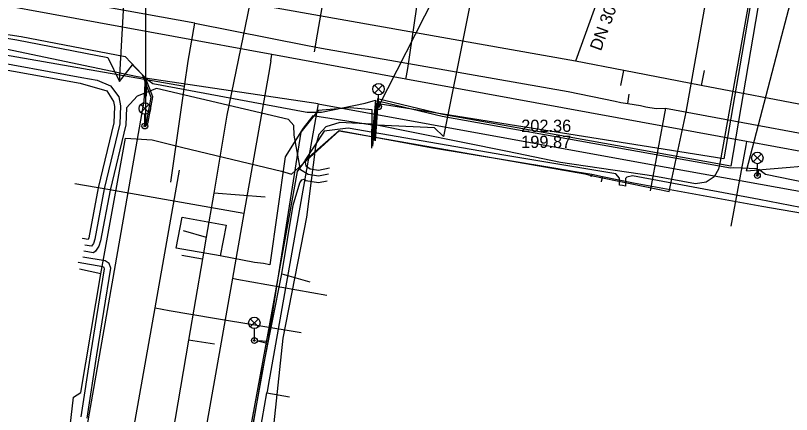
# Model space of a CAD drawing. Extents: x -596228 to -595156, y -1161235 to -1159373.
# Drawn here: x -595929.1 to -595878.3, y -1160349.7 to -1160323.7 of the extents above; entities that cross this region are included whole.
import ezdxf

# ---------------------------------------------------------------- set-up
doc = ezdxf.new("R2010")
doc.units = 0
for name, color, linetype in [('Vrstva 1', 7, 'Continuous'), ('Vrstva 12', 7, 'Continuous'), ('Vrstva 14', 7, 'Continuous'), ('Vrstva 16', 7, 'Continuous'), ('Vrstva 19', 7, 'Continuous'), ('Vrstva 33', 7, 'Continuous'), ('Vrstva 4', 7, 'Continuous'), ('Vrstva 42', 7, 'Continuous'), ('Vrstva 44', 7, 'Continuous'), ('Vrstva 54', 7, 'Continuous'), ('Vrstva 55', 7, 'Continuous'), ('Vrstva 58', 7, 'Continuous'), ('Vrstva 9', 7, 'Continuous')]:
    doc.layers.add(name, color=color, linetype=linetype)

msp = doc.modelspace()

# ---------------------------------------------------------------- linework, layer by layer
at = {"layer": 'Vrstva 1'}
for p, q in [((-595888.65, -1160316.04), (-595892.47, -1160326.63)), ((-595888.649, -1160316.044), (-595892.47, -1160326.63)), ((-595912.78, -1160335.52), (-595916.141, -1160335.27)), ((-595918.228, -1160339.316), (-595916.873, -1160339.558))]:
    msp.add_line(p, q, dxfattribs=at)
at = {"layer": 'Vrstva 12'}
for p, q in [((-595921.13, -1160327.66), (-595929.73, -1160325.84)), ((-595920.63, -1160327.74), (-595921.13, -1160327.66)), ((-595920.63, -1160327.74), (-595920.7, -1160329.26)), ((-595909.31, -1160329.42), (-595920.63, -1160327.74)), ((-595909.31, -1160329.42), (-595912.58, -1160347.84)), ((-595891.4, -1160334.03), (-595890.71, -1160334.18)), ((-595890.71, -1160334.18), (-595890.8, -1160334.52)), ((-595913.63, -1160353.77), (-595912.66, -1160348.33)), ((-595912.66, -1160348.33), (-595911.19, -1160348.59))]:
    msp.add_line(p, q, dxfattribs=at)
for points in [[(-595920.7, -1160329.26), (-595926.32, -1160361.22), (-595928.48, -1160360.84)], [(-595909.31, -1160329.42), (-595887.62, -1160333.37), (-595870.92, -1160336.38), (-595851.25, -1160339.95)], [(-595913.91, -1160351.66), (-595913.82, -1160351.17), (-595912.54, -1160344.18), (-595910.66, -1160333.84), (-595910.07, -1160333.04), (-595907.93, -1160331.17), (-595901.94, -1160332.28), (-595894.02, -1160333.59)], [(-595894.02, -1160333.59), (-595892.36, -1160333.86), (-595891.4, -1160334.03)], [(-595890.71, -1160334.18), (-595888.67, -1160334.6), (-595880.28, -1160336.12), (-595874.32, -1160337.13), (-595873.61, -1160337.32)], [(-595912.58, -1160347.84), (-595912.63, -1160348.13), (-595912.66, -1160348.33)]]:
    msp.add_lwpolyline(points, dxfattribs=at)
at = {"layer": 'Vrstva 14'}
for p, q in [((-595912.4, -1160326.61), (-595912.327, -1160326.199)), ((-595912.4, -1160326.61), (-595912.56, -1160327.515)), ((-595903.564, -1160327.806), (-595903.525, -1160327.591))]:
    msp.add_line(p, q, dxfattribs=at)
for points in [[(-595903.525, -1160327.591), (-595903.438, -1160327.11), (-595895.992, -1160276.218), (-595895.362, -1160271.913), (-595894.416, -1160266.829), (-595893.077, -1160257.958), (-595892.847, -1160256.335), (-595887.94, -1160223.167), (-595881.65, -1160186.81), (-595876.814, -1160159.541), (-595869.649, -1160117.522), (-595863.209, -1160078.856), (-595858.091, -1160048.124), (-595857.576, -1160045.207), (-595855.994, -1160045.422), (-595855.543, -1160042.523), (-595857.05, -1160042.292), (-595850.5, -1160006.311), (-595840.026, -1160007.969)], [(-595912.327, -1160326.199), (-595944.525, -1160320.296), (-595964.314, -1160316.668), (-595981.5, -1160313.518), (-595993.326, -1160311.35), (-595998.98, -1160310.314), (-596012.243, -1160307.882), (-596018.266, -1160306.788), (-596020.483, -1160306.371), (-596031.546, -1160304.536), (-596031.549, -1160304.535)], [(-595903.564, -1160327.806), (-595911.269, -1160326.394), (-595912.327, -1160326.199)], [(-595912.56, -1160327.515), (-595914.166, -1160336.603), (-595914.913, -1160340.831), (-595917.737, -1160356.816), (-595918.916, -1160363.488), (-595919.224, -1160365.229), (-595921.006, -1160375.317), (-595921.479, -1160377.993), (-595922.856, -1160385.788), (-595923.243, -1160387.979), (-595923.737, -1160390.772), (-595924.81, -1160396.848), (-595925.361, -1160399.964), (-595925.421, -1160400.293), (-595926.258, -1160405.043), (-595926.951, -1160408.967), (-595927.505, -1160412.107), (-595927.792, -1160413.727), (-595928.476, -1160417.596), (-595928.908, -1160420.384), (-595929.827, -1160426.314), (-595930.81, -1160432.66), (-595928.636, -1160435.746)], [(-595796.62, -1160347.3), (-595824.314, -1160342.334), (-595828.542, -1160341.559), (-595835.203, -1160340.338), (-595848.129, -1160337.968), (-595856.324, -1160336.466), (-595859.13, -1160335.952), (-595871.786, -1160333.632), (-595881.289, -1160331.89), (-595903.564, -1160327.806)], [(-595881.289, -1160331.89), (-595881.335, -1160332.141), (-595882.304, -1160337.424)], [(-595914.166, -1160336.603), (-595923.07, -1160335.03), (-595925.227, -1160334.649)], [(-595914.913, -1160340.831), (-595914.634, -1160340.881), (-595908.728, -1160341.924)]]:
    msp.add_lwpolyline(points, dxfattribs=at)
at = {"layer": 'Vrstva 16'}
for p, q in [((-595889.042, -1160329.399), (-595888.956, -1160328.802)), ((-595886.59, -1160329.7), (-595887.58, -1160335.11))]:
    msp.add_line(p, q, dxfattribs=at)
for points in [[(-595917.38, -1160324.14), (-595937.03, -1160320.6), (-595938.02, -1160320.43), (-595944.42, -1160319.31), (-595959.68, -1160316.64), (-595967.05, -1160315.3), (-595979.197, -1160313.085)], [(-595918.953, -1160334.548), (-595918.06, -1160328.3), (-595917.82, -1160326.64), (-595917.38, -1160324.14)], [(-595917.38, -1160324.14), (-595910, -1160325.618), (-595909.091, -1160325.778), (-595892.958, -1160328.622), (-595889.882, -1160329.258), (-595889.508, -1160329.332), (-595889.042, -1160329.399), (-595888.212, -1160329.541), (-595887.856, -1160329.621), (-595887.183, -1160329.739), (-595886.59, -1160329.7), (-595871.98, -1160332.41), (-595863.04, -1160334.1), (-595856.28, -1160335.39), (-595846.15, -1160336.98), (-595838.77, -1160338.11)], [(-595918.06, -1160328.3), (-595938.26, -1160324.76), (-595938.46, -1160325.84)]]:
    msp.add_lwpolyline(points, dxfattribs=at)
at = {"layer": 'Vrstva 19'}
for points in [[(-595906.726, -1160309.776), (-595909.359, -1160324.873), (-595909.569, -1160326.017)], [(-595937.007, -1160434.731), (-595933.869, -1160420.107), (-595932.707, -1160414.408), (-595931.819, -1160409.92), (-595931.488, -1160408.037), (-595930.76, -1160403.887), (-595930.162, -1160400.514), (-595929.486, -1160396.69), (-595928.868, -1160393.202), (-595928.299, -1160389.952), (-595928.122, -1160388.956), (-595925.699, -1160375.221), (-595925.424, -1160373.699), (-595923.915, -1160365.05), (-595923.881, -1160364.906), (-595921.628, -1160352.081), (-595919.973, -1160342.771), (-595918.382, -1160333.761)], [(-595919.973, -1160342.771), (-595919.056, -1160342.938), (-595916.097, -1160343.43), (-595910.412, -1160344.374)]]:
    msp.add_lwpolyline(points, dxfattribs=at)
at = {"layer": 'Vrstva 33'}
for p, q in [((-595905.617, -1160328.194), (-595905.087, -1160328.724)), ((-595905.617, -1160328.724), (-595905.087, -1160328.194)), ((-595905.352, -1160329.609), (-595905.352, -1160328.834)), ((-595920.909, -1160329.462), (-595920.379, -1160329.992)), ((-595920.909, -1160329.992), (-595920.379, -1160329.462)), ((-595920.644, -1160330.877), (-595920.644, -1160330.102)), ((-595880.835, -1160332.697), (-595880.305, -1160333.227)), ((-595880.835, -1160333.227), (-595880.305, -1160332.697)), ((-595880.57, -1160334.112), (-595880.57, -1160333.337)), ((-595913.745, -1160343.485), (-595913.215, -1160344.015)), ((-595913.745, -1160344.015), (-595913.215, -1160343.485)), ((-595913.48, -1160344.9), (-595913.48, -1160344.125))]:
    msp.add_line(p, q, dxfattribs=at)
for centre, radius in [((-595905.352, -1160328.459), 0.375), ((-595920.644, -1160329.727), 0.375), ((-595905.352, -1160329.609), 0.19), ((-595905.352, -1160329.609), 0.05), ((-595920.644, -1160330.877), 0.19), ((-595920.644, -1160330.877), 0.05), ((-595880.57, -1160332.962), 0.375), ((-595880.57, -1160334.112), 0.19), ((-595880.57, -1160334.112), 0.05), ((-595913.48, -1160343.75), 0.375), ((-595913.48, -1160344.9), 0.19), ((-595913.48, -1160344.9), 0.05)]:
    msp.add_circle(centre, radius, dxfattribs=at)
at = {"layer": 'Vrstva 42'}
msp.add_line((-595911.68, -1160340.548), (-595909.852, -1160341.061), dxfattribs=at)
for points in [[(-595932.932, -1160324.581), (-595929.027, -1160325.242), (-595923.071, -1160326.404), (-595922.307, -1160327.96), (-595920.903, -1160303.182), (-595919.478, -1160301.216), (-595901.62, -1160304.641), (-595898.195, -1160305.065), (-595896.735, -1160305.447), (-595895.931, -1160305.565), (-595896.41, -1160308.706), (-595896.64, -1160309.26), (-595901.111, -1160331.564), (-595901.699, -1160330.991), (-595905.91, -1160330.801), (-595909.662, -1160330.217), (-595910.286, -1160331.011), (-595911.466, -1160332.883), (-595912.47, -1160339.95), (-595912.872, -1160339.865)], [(-595945.819, -1160324.546), (-595945.748, -1160324.061), (-595945.592, -1160324.019), (-595943.697, -1160324.265), (-595936.771, -1160325.507), (-595935.472, -1160325.74), (-595931.446, -1160326.474), (-595924.764, -1160327.692), (-595923.765, -1160327.878), (-595922.887, -1160328.25), (-595922.352, -1160328.96), (-595922.237, -1160329.564), (-595922.28, -1160330.732), (-595923.313, -1160334.991), (-595923.924, -1160338.282), (-595924.007, -1160338.558), (-595924.133, -1160338.73), (-595924.561, -1160338.655)], [(-595935.565, -1160326.153), (-595924.874, -1160328.07), (-595923.125, -1160328.568), (-595922.7, -1160329.267), (-595922.638, -1160329.594), (-595922.678, -1160330.677), (-595923.704, -1160334.907), (-595924.313, -1160338.188), (-595924.343, -1160338.288), (-595924.722, -1160338.221), (-595924.726, -1160338.244)], [(-595922.307, -1160327.96), (-595921.458, -1160326.877), (-595920.565, -1160327.77), (-595920.554, -1160328.916)], [(-595908.631, -1160334.031), (-595909.283, -1160334.161), (-595909.964, -1160334.052), (-595910.47, -1160333.734), (-595910.556, -1160333.262), (-595910.881, -1160331.468), (-595910.888, -1160330.838), (-595911.243, -1160330.449), (-595919.891, -1160328.424), (-595921.155, -1160328.93), (-595921.842, -1160329.685), (-595921.882, -1160330.787), (-595922.922, -1160335.075), (-595923.535, -1160338.376), (-595923.644, -1160338.739), (-595923.873, -1160339.053), (-595924.003, -1160339.16), (-595924.631, -1160339.049)], [(-595872.34, -1160337.244), (-595880.463, -1160335.669), (-595888.734, -1160334.137), (-595889.101, -1160334.217), (-595889.194, -1160334.307), (-595889.203, -1160334.813), (-595889.399, -1160334.773), (-595889.599, -1160334.743), (-595889.587, -1160334.279), (-595889.825, -1160334.011), (-595897.161, -1160332.783), (-595907.35, -1160331.02), (-595908.902, -1160331.217), (-595910.173, -1160333.129), (-595910.108, -1160333.489), (-595909.82, -1160333.67), (-595909.291, -1160333.755), (-595908.556, -1160333.609)], [(-595911.68, -1160340.548), (-595910.946, -1160336.044), (-595910.501, -1160334.597), (-595910.383, -1160334.386), (-595910.226, -1160334.36), (-595910.108, -1160334.434), (-595909.275, -1160334.567), (-595908.706, -1160334.453)], [(-595912.872, -1160339.865), (-595913.463, -1160339.796), (-595915.71, -1160339.36), (-595918.595, -1160338.851), (-595918.205, -1160336.826), (-595915.326, -1160337.367), (-595915.71, -1160339.36)], [(-595924.413, -1160349.983), (-595923.788, -1160345.83), (-595922.869, -1160340.179), (-595922.985, -1160339.859), (-595923.25, -1160339.697), (-595924.7, -1160339.442)], [(-595924.805, -1160349.897), (-595924.184, -1160345.768), (-595923.281, -1160340.217), (-595923.313, -1160340.127), (-595923.393, -1160340.079), (-595924.999, -1160339.795), (-595924.995, -1160339.771)], [(-595915.042, -1160370.404), (-595916.313, -1160370.234), (-595916.762, -1160370.071), (-595916.917, -1160369.718), (-595916.266, -1160365.38), (-595916.097, -1160364.525), (-595914.555, -1160356.21), (-595912.957, -1160346.91), (-595911.68, -1160340.548)]]:
    msp.add_lwpolyline(points, dxfattribs=at)
at = {"layer": 'Vrstva 44'}
msp.add_lwpolyline([(-595879.564, -1160313.987), (-595883.002, -1160333.198), (-595883.107, -1160333.686), (-595883.405, -1160334.19), (-595883.921, -1160334.544), (-595884.612, -1160334.658), (-595887.338, -1160334.157), (-595893.448, -1160333.257), (-595896.919, -1160332.531), (-595905.801, -1160330.747), (-595907.892, -1160330.653), (-595908.804, -1160330.924), (-595909.261, -1160331.432), (-595909.489, -1160332.217), (-595910.064, -1160336.838), (-595911.622, -1160344.756), (-595912.375, -1160351.925)], dxfattribs=at)
at = {"layer": 'Vrstva 54'}
for p, q in [((-595920.59, -1160330.87), (-595920.58, -1160309.17)), ((-595905.35, -1160329.62), (-595897.2, -1160313.58)), ((-595879.08, -1160325.37), (-595878.31, -1160322.44)), ((-595881.29, -1160333.8), (-595879.08, -1160325.37)), ((-595881.29, -1160333.8), (-595848.05, -1160331.08))]:
    msp.add_line(p, q, dxfattribs=at)
at = {"layer": 'Vrstva 55'}
for points in [[(-595899.01, -1160302.475), (-595898.851, -1160302.449), (-595898.714, -1160302.619), (-595898.303, -1160303.953), (-595897.422, -1160304.755), (-595897.682, -1160307.978), (-595897.18, -1160308.657), (-595895.88, -1160309.31), (-595895.773, -1160309.364), (-595892.5, -1160311.007), (-595890.732, -1160311.409), (-595881.701, -1160313.199), (-595878.928, -1160313.669), (-595882.299, -1160333.495), (-595901.158, -1160330.111), (-595905.425, -1160329.09), (-595905.669, -1160331.811)], [(-595901.76, -1160303.617), (-595900.5, -1160305.57), (-595899.058, -1160306.768), (-595898.651, -1160307.058), (-595897.37, -1160308.863), (-595892.714, -1160311.365), (-595879.502, -1160313.984), (-595882.762, -1160333.016), (-595905.518, -1160329.407), (-595905.751, -1160332.201)], [(-595937.08, -1160323.76), (-595928.74, -1160325.02), (-595921.94, -1160326.33), (-595920.809, -1160327.51), (-595920.252, -1160328.986), (-595920.539, -1160330.587), (-595920.558, -1160330.665), (-595920.54, -1160330.84), (-595920.442, -1160330.694), (-595920.421, -1160330.613), (-595920.128, -1160328.974), (-595920.598, -1160327.731), (-595920.56, -1160327.77), (-595920.13, -1160328.09), (-595910.145, -1160329.939), (-595910.03, -1160329.96), (-595909.09, -1160329.98), (-595906.22, -1160329.38), (-595905.554, -1160329.186), (-595905.787, -1160331.789)], [(-595905.55, -1160331.833), (-595905.386, -1160329.409), (-595905.312, -1160329.246), (-595905.371, -1160329.484), (-595905.32, -1160329.62), (-595905.238, -1160329.507), (-595905.194, -1160329.268), (-595901.182, -1160330.229), (-595882.321, -1160333.612), (-595882.11, -1160333.59), (-595880.6, -1160333.648), (-595880.615, -1160334.016), (-595880.56, -1160334.15), (-595880.494, -1160334.01), (-595880.482, -1160333.692), (-595880.03, -1160334.02), (-595870.57, -1160335.97)], [(-595905.802, -1160332.325), (-595905.763, -1160329.822), (-595907.213, -1160329.696), (-595909.31, -1160329.87), (-595910.44, -1160331.28), (-595912.59, -1160344.96), (-595913.28, -1160344.91), (-595912.62, -1160345.07), (-595917.45, -1160371.78), (-595918.01, -1160371.63), (-595917.64, -1160371.78), (-595921.92, -1160396.92), (-595922.59, -1160396.76), (-595922.11, -1160397.08), (-595927.82, -1160426.66)]]:
    msp.add_lwpolyline(points, dxfattribs=at)
at = {"layer": 'Vrstva 58'}
for p, q in [((-595891.4, -1160334.03), (-595891.4, -1160334.08)), ((-595891.4, -1160334.03), (-595890.71, -1160334.18)), ((-595891.44, -1160334.1), (-595891.463, -1160334.194)), ((-595890.71, -1160334.18), (-595890.8, -1160334.51)), ((-595923.52, -1160340.53), (-595924.91, -1160340.23))]:
    msp.add_line(p, q, dxfattribs=at)
for points in [[(-595891.44, -1160334.1), (-595886.33, -1160335.16), (-595885.22, -1160329.96), (-595882.82, -1160316.47), (-595882.62, -1160313.06), (-595882.78, -1160310.83), (-595882.43, -1160307.29), (-595882.41, -1160306.83), (-595882.47, -1160306.41), (-595886.29, -1160305.97), (-595886.8, -1160305.8), (-595887.07, -1160305.23), (-595887.44, -1160303.71), (-595887.97, -1160301.67), (-595889.06, -1160300.62), (-595891.12, -1160299.25), (-595892.49, -1160297.74), (-595894.63, -1160293.46), (-595894.95, -1160291.64), (-595894.36, -1160287.89), (-595892.89, -1160279.48), (-595889.65, -1160261.01)], [(-595925.53, -1160350.5), (-595925.31, -1160348.61), (-595924.84, -1160348.3), (-595923.52, -1160340.53), (-595921.9, -1160331.66), (-595920.16, -1160331.78), (-595918.16, -1160332.29), (-595911.7, -1160333.82), (-595911.04, -1160334.03), (-595907.93, -1160331.19), (-595891.86, -1160334.01), (-595891.44, -1160334.1), (-595886.33, -1160335.16), (-595885.22, -1160329.96), (-595882.82, -1160316.47)], [(-595923.52, -1160340.53), (-595921.9, -1160331.66), (-595920.16, -1160331.78), (-595918.16, -1160332.29), (-595911.7, -1160333.82), (-595911.04, -1160334.03), (-595907.93, -1160331.19), (-595891.86, -1160334.01), (-595891.44, -1160334.1)], [(-595914.4, -1160353.03), (-595913.91, -1160351.66), (-595913.82, -1160351.17), (-595912.54, -1160344.18), (-595910.66, -1160333.84), (-595910.07, -1160333.04), (-595907.93, -1160331.17), (-595901.94, -1160332.28), (-595894.02, -1160333.59), (-595892.36, -1160333.86), (-595891.4, -1160334.03)], [(-595890.71, -1160334.18), (-595888.67, -1160334.6), (-595880.28, -1160336.12), (-595874.32, -1160337.13), (-595873.61, -1160337.32)], [(-595926.67, -1160350.37), (-595925.53, -1160350.5), (-595925.31, -1160348.61), (-595924.84, -1160348.3), (-595923.52, -1160340.53)]]:
    msp.add_lwpolyline(points, dxfattribs=at)
at = {"layer": 'Vrstva 9'}
for p, q in [((-595913.78, -1160322.86), (-595915.27, -1160330.17)), ((-595892.47, -1160326.63), (-595913.78, -1160322.86)), ((-595889.502, -1160328.221), (-595889.313, -1160327.239)), ((-595884.057, -1160327.235), (-595884.246, -1160328.217)), ((-595918.144, -1160337.711), (-595916.632, -1160338.149)), ((-595916.077, -1160345.143), (-595917.782, -1160344.881))]:
    msp.add_line(p, q, dxfattribs=at)
for points in [[(-595874.28, -1160330.14), (-595875.458, -1160329.913), (-595876.951, -1160329.625), (-595884.246, -1160328.217), (-595889.313, -1160327.239), (-595892.47, -1160326.63)], [(-595915.27, -1160330.17), (-595916.141, -1160335.27), (-595916.632, -1160338.149), (-595916.873, -1160339.558), (-595917.782, -1160344.881), (-595919.729, -1160356.286)]]:
    msp.add_lwpolyline(points, dxfattribs=at)

# ---------------------------------------------------------------- texts
at = {"layer": 'Vrstva 12'}
for s, p in [('202.36', (-595896.021, -1160331.259)), ('199.87', (-595896.021, -1160332.309))]:
    msp.add_text(s, height=0.8, dxfattribs=at).set_placement(p)
at = {"layer": 'Vrstva 4'}
msp.add_text('DN 300 BET', height=0.8, rotation=70, dxfattribs=at).set_placement((-595890.807, -1160326.016))

doc.saveas('drawing.dxf')
